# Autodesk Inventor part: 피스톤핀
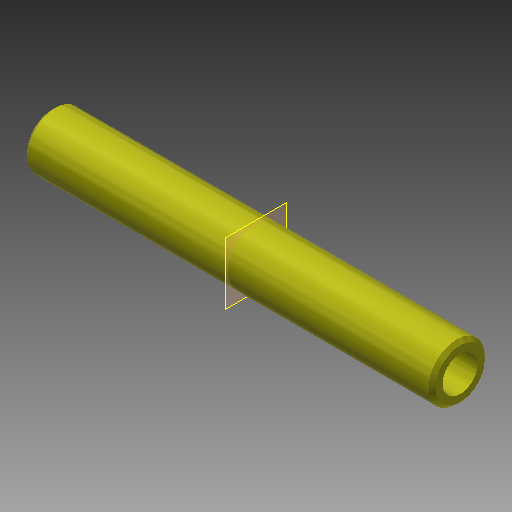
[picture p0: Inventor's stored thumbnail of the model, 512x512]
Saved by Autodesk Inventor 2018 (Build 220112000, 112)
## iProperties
Created: 2016-11
Part Number: 피스톤핀
Material: 강철, 탄소
Document SubType Name: Modeling
Designer: mduedu
Density: 7.87 g/cm^3
Mass: 13.9342 g
Surface Area: 24.1465 cm^2
Volume: 1.77055 cm^3
Appearance: 노란색
Author: mduedu
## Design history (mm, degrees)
sketch "스케치1"
  geometry: C1 r 2.5 at (0, 0); C2 r 4 at (0, 0); 1 further point
  constraints: 2 centre point, 2 coincident
  dimensions: "d0" = 5 diameter of C1; "d1" = 8 diameter of C2
extrude "돌출1" new body sketch "스케치1" stored distance "d2" = 58; taper "d3" = 0 deg
chamfer "모따기1" distance "d4" = 0.5; stored, may be unused: second distance "d5" = 2, angle "d6" = 45 deg
node "솔리드1"
